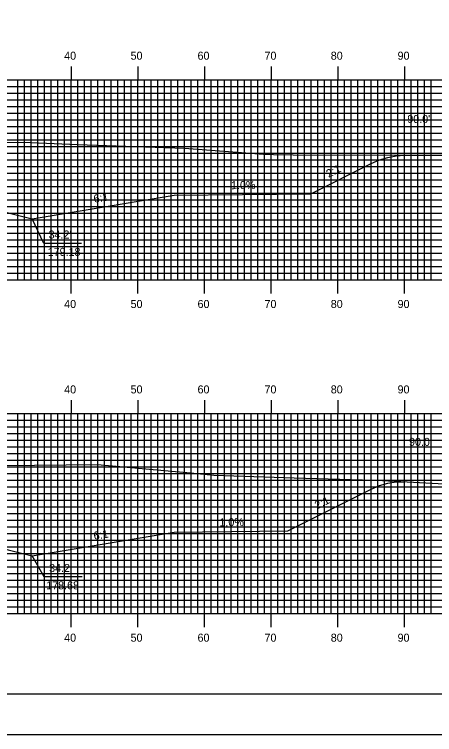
# Model space of a CAD drawing. Extents: x 1797207 to 1797550, y 442591 to 442811.
# Drawn here: x 1797404.4 to 1797467.5, y 442590.5 to 442698.5 of the extents above; entities that cross this region are included whole.
import ezdxf

# ---------------------------------------------------------------- set-up
doc = ezdxf.new("R2010")
doc.units = 0
for name, color, linetype in [('ANNOTATION', 7, 'Continuous'), ('BORDER', 7, 'Continuous'), ('D_Roadway_Centerline', 7, 'Continuous'), ('D_Roadway_SlopeLines', 7, 'Continuous'), ('D_Text_Standard', 7, 'Continuous'), ('H_V ANNOTATION', 7, 'Continuous'), ('MAJOR', 7, 'Continuous'), ('MINOR', 7, 'Continuous'), ('PLOT BOUNDARY', 7, 'Continuous'), ('S_Roadway_Centerline', 7, 'Continuous')]:
    doc.layers.add(name, color=color, linetype=linetype)

msp = doc.modelspace()

# ---------------------------------------------------------------- linework, layer by layer
at = {"layer": 'ANNOTATION'}
for points in [[(1797414.52, 442664.15), (1797408.83, 442664.15), (1797407.11, 442667.85)], [(1797414.6, 442614.18), (1797408.91, 442614.18), (1797407.11, 442617.35)]]:
    msp.add_lwpolyline(points, dxfattribs=at)
at = {"layer": 'BORDER'}
msp.add_lwpolyline([(1797223.33, 442596.67), (1797543.33, 442596.67), (1797543.33, 442806.67), (1797223.33, 442806.67)], close=True, dxfattribs=at)
at = {"layer": 'D_Roadway_Centerline'}
for points in [[(1797282.93, 442682.01), (1797284.18, 442681.93), (1797285.43, 442681.68), (1797286.68, 442681.29), (1797287.93, 442680.74), (1797305.44, 442671.99), (1797317.5, 442671.87), (1797338.76, 442668.33), (1797342.76, 442669.33), (1797352.93, 442671.87), (1797360.93, 442672.19), (1797372.93, 442671.95), (1797384.93, 442671.71), (1797392.93, 442671.39), (1797403.11, 442668.85), (1797407.11, 442667.85), (1797428.37, 442671.39), (1797448.91, 442671.59), (1797457.93, 442676.11), (1797459.18, 442676.65), (1797460.43, 442677.04), (1797461.68, 442677.28), (1797462.93, 442677.35)], [(1797282.93, 442632.85), (1797284.18, 442632.77), (1797285.43, 442632.53), (1797286.68, 442632.14), (1797287.93, 442631.59), (1797308.19, 442621.46), (1797317.5, 442621.37), (1797338.76, 442617.83), (1797342.76, 442618.83), (1797352.93, 442621.37), (1797360.93, 442621.69), (1797372.93, 442621.45), (1797384.93, 442621.21), (1797392.93, 442620.89), (1797403.11, 442618.35), (1797407.11, 442617.35), (1797428.37, 442620.89), (1797445.43, 442621.06), (1797457.93, 442627.31), (1797459.18, 442627.85), (1797460.43, 442628.22), (1797461.68, 442628.41), (1797462.93, 442628.43)]]:
    msp.add_lwpolyline(points, dxfattribs=at)
at = {"layer": 'D_Roadway_SlopeLines'}
for points in [[(1797428.37, 442671.39), (1797448.91, 442671.59), (1797457.93, 442676.11), (1797459.18, 442676.65), (1797460.43, 442677.04), (1797461.68, 442677.28), (1797462.93, 442677.35)], [(1797392.93, 442671.39), (1797407.11, 442667.85)], [(1797407.11, 442667.85), (1797428.37, 442671.39)], [(1797428.37, 442620.89), (1797445.43, 442621.06), (1797457.93, 442627.31), (1797459.18, 442627.85), (1797460.43, 442628.22), (1797461.68, 442628.41), (1797462.93, 442628.43)], [(1797392.93, 442620.89), (1797407.11, 442617.35)], [(1797407.11, 442617.35), (1797428.37, 442620.89)]]:
    msp.add_lwpolyline(points, dxfattribs=at)
at = {"layer": 'MAJOR'}
for p, q in [((1797412.93, 442690.67), (1797412.93, 442688.67)), ((1797422.93, 442690.67), (1797422.93, 442688.67)), ((1797432.93, 442690.67), (1797432.93, 442688.67)), ((1797442.93, 442690.67), (1797442.93, 442688.67)), ((1797452.93, 442690.67), (1797452.93, 442688.67)), ((1797462.93, 442690.67), (1797462.93, 442688.67)), ((1797232.93, 442688.67), (1797512.93, 442688.67)), ((1797232.93, 442688.67), (1797512.93, 442688.67)), ((1797412.93, 442658.67), (1797412.93, 442688.67)), ((1797422.93, 442658.67), (1797422.93, 442688.67)), ((1797432.93, 442658.67), (1797432.93, 442688.67)), ((1797442.93, 442658.67), (1797442.93, 442688.67)), ((1797452.93, 442658.67), (1797452.93, 442688.67)), ((1797462.93, 442658.67), (1797462.93, 442688.67)), ((1797232.93, 442683.67), (1797512.93, 442683.67)), ((1797232.93, 442678.67), (1797512.93, 442678.67)), ((1797232.93, 442673.67), (1797512.93, 442673.67)), ((1797232.93, 442668.67), (1797512.93, 442668.67)), ((1797232.93, 442663.67), (1797512.93, 442663.67)), ((1797232.93, 442658.67), (1797512.93, 442658.67)), ((1797232.93, 442658.67), (1797512.93, 442658.67)), ((1797412.93, 442656.66), (1797412.93, 442658.67)), ((1797422.93, 442656.66), (1797422.93, 442658.67)), ((1797432.93, 442656.66), (1797432.93, 442658.67)), ((1797442.93, 442656.66), (1797442.93, 442658.67)), ((1797452.93, 442656.66), (1797452.93, 442658.67)), ((1797462.93, 442656.66), (1797462.93, 442658.67)), ((1797412.93, 442640.67), (1797412.93, 442638.67)), ((1797422.93, 442640.67), (1797422.93, 442638.67)), ((1797432.93, 442640.67), (1797432.93, 442638.67)), ((1797442.93, 442640.67), (1797442.93, 442638.67)), ((1797452.93, 442640.67), (1797452.93, 442638.67)), ((1797462.93, 442640.67), (1797462.93, 442638.67)), ((1797232.93, 442638.67), (1797512.93, 442638.67)), ((1797232.93, 442638.67), (1797512.93, 442638.67)), ((1797412.93, 442608.67), (1797412.93, 442638.67)), ((1797422.93, 442608.67), (1797422.93, 442638.67)), ((1797432.93, 442608.67), (1797432.93, 442638.67)), ((1797442.93, 442608.67), (1797442.93, 442638.67)), ((1797452.93, 442608.67), (1797452.93, 442638.67)), ((1797462.93, 442608.67), (1797462.93, 442638.67)), ((1797232.93, 442633.67), (1797512.93, 442633.67)), ((1797232.93, 442628.67), (1797512.93, 442628.67)), ((1797232.93, 442623.67), (1797512.93, 442623.67)), ((1797232.93, 442618.67), (1797512.93, 442618.67)), ((1797232.93, 442613.67), (1797512.93, 442613.67)), ((1797232.93, 442608.67), (1797512.93, 442608.67)), ((1797232.93, 442608.67), (1797512.93, 442608.67)), ((1797412.93, 442606.66), (1797412.93, 442608.67)), ((1797422.93, 442606.66), (1797422.93, 442608.67)), ((1797432.93, 442606.66), (1797432.93, 442608.67)), ((1797442.93, 442606.66), (1797442.93, 442608.67)), ((1797452.93, 442606.66), (1797452.93, 442608.67)), ((1797462.93, 442606.66), (1797462.93, 442608.67))]:
    msp.add_line(p, q, dxfattribs=at)
at = {"layer": 'MINOR'}
for p, q in [((1797404.93, 442658.67), (1797404.93, 442688.67)), ((1797405.93, 442658.67), (1797405.93, 442688.67)), ((1797406.93, 442658.67), (1797406.93, 442688.67)), ((1797407.93, 442658.67), (1797407.93, 442688.67)), ((1797408.93, 442658.67), (1797408.93, 442688.67)), ((1797409.93, 442658.67), (1797409.93, 442688.67)), ((1797410.93, 442658.67), (1797410.93, 442688.67)), ((1797411.93, 442658.67), (1797411.93, 442688.67)), ((1797413.93, 442658.67), (1797413.93, 442688.67)), ((1797414.93, 442658.67), (1797414.93, 442688.67)), ((1797415.93, 442658.67), (1797415.93, 442688.67)), ((1797416.93, 442658.67), (1797416.93, 442688.67)), ((1797417.93, 442658.67), (1797417.93, 442688.67)), ((1797418.93, 442658.67), (1797418.93, 442688.67)), ((1797419.93, 442658.67), (1797419.93, 442688.67)), ((1797420.93, 442658.67), (1797420.93, 442688.67)), ((1797421.93, 442658.67), (1797421.93, 442688.67)), ((1797423.93, 442658.67), (1797423.93, 442688.67)), ((1797424.93, 442658.67), (1797424.93, 442688.67)), ((1797425.93, 442658.67), (1797425.93, 442688.67)), ((1797426.93, 442658.67), (1797426.93, 442688.67)), ((1797427.93, 442658.67), (1797427.93, 442688.67)), ((1797428.93, 442658.67), (1797428.93, 442688.67)), ((1797429.93, 442658.67), (1797429.93, 442688.67)), ((1797430.93, 442658.67), (1797430.93, 442688.67)), ((1797431.93, 442658.67), (1797431.93, 442688.67)), ((1797433.93, 442658.67), (1797433.93, 442688.67)), ((1797434.93, 442658.67), (1797434.93, 442688.67)), ((1797435.93, 442658.67), (1797435.93, 442688.67)), ((1797436.93, 442658.67), (1797436.93, 442688.67)), ((1797437.93, 442658.67), (1797437.93, 442688.67)), ((1797438.93, 442658.67), (1797438.93, 442688.67)), ((1797439.93, 442658.67), (1797439.93, 442688.67)), ((1797440.93, 442658.67), (1797440.93, 442688.67)), ((1797441.93, 442658.67), (1797441.93, 442688.67)), ((1797443.93, 442658.67), (1797443.93, 442688.67)), ((1797444.93, 442658.67), (1797444.93, 442688.67)), ((1797445.93, 442658.67), (1797445.93, 442688.67)), ((1797446.93, 442658.67), (1797446.93, 442688.67)), ((1797447.93, 442658.67), (1797447.93, 442688.67)), ((1797448.93, 442658.67), (1797448.93, 442688.67)), ((1797449.93, 442658.67), (1797449.93, 442688.67)), ((1797450.93, 442658.67), (1797450.93, 442688.67)), ((1797451.93, 442658.67), (1797451.93, 442688.67)), ((1797453.93, 442658.67), (1797453.93, 442688.67)), ((1797454.93, 442658.67), (1797454.93, 442688.67)), ((1797455.93, 442658.67), (1797455.93, 442688.67)), ((1797456.93, 442658.67), (1797456.93, 442688.67)), ((1797457.93, 442658.67), (1797457.93, 442688.67)), ((1797458.93, 442658.67), (1797458.93, 442688.67)), ((1797459.93, 442658.67), (1797459.93, 442688.67)), ((1797460.93, 442658.67), (1797460.93, 442688.67)), ((1797461.93, 442658.67), (1797461.93, 442688.67)), ((1797463.93, 442658.67), (1797463.93, 442688.67)), ((1797464.93, 442658.67), (1797464.93, 442688.67)), ((1797465.93, 442658.67), (1797465.93, 442688.67)), ((1797466.93, 442658.67), (1797466.93, 442688.67)), ((1797232.93, 442687.67), (1797512.93, 442687.67)), ((1797232.93, 442686.67), (1797512.93, 442686.67)), ((1797232.93, 442685.67), (1797512.93, 442685.67)), ((1797232.93, 442684.67), (1797512.93, 442684.67)), ((1797232.93, 442682.67), (1797512.93, 442682.67)), ((1797232.93, 442681.67), (1797512.93, 442681.67)), ((1797232.93, 442680.67), (1797512.93, 442680.67)), ((1797232.93, 442679.67), (1797512.93, 442679.67)), ((1797232.93, 442677.67), (1797512.93, 442677.67)), ((1797232.93, 442676.67), (1797512.93, 442676.67)), ((1797232.93, 442675.67), (1797512.93, 442675.67)), ((1797232.93, 442674.67), (1797512.93, 442674.67)), ((1797232.93, 442672.67), (1797512.93, 442672.67)), ((1797232.93, 442671.67), (1797512.93, 442671.67)), ((1797232.93, 442670.67), (1797512.93, 442670.67)), ((1797232.93, 442669.67), (1797512.93, 442669.67)), ((1797232.93, 442667.67), (1797512.93, 442667.67)), ((1797232.93, 442666.67), (1797512.93, 442666.67)), ((1797232.93, 442665.67), (1797512.93, 442665.67)), ((1797232.93, 442664.67), (1797512.93, 442664.67)), ((1797232.93, 442662.67), (1797512.93, 442662.67)), ((1797232.93, 442661.67), (1797512.93, 442661.67)), ((1797232.93, 442660.67), (1797512.93, 442660.67)), ((1797232.93, 442659.67), (1797512.93, 442659.67)), ((1797404.93, 442608.67), (1797404.93, 442638.67)), ((1797405.93, 442608.67), (1797405.93, 442638.67)), ((1797406.93, 442608.67), (1797406.93, 442638.67)), ((1797407.93, 442608.67), (1797407.93, 442638.67)), ((1797408.93, 442608.67), (1797408.93, 442638.67)), ((1797409.93, 442608.67), (1797409.93, 442638.67)), ((1797410.93, 442608.67), (1797410.93, 442638.67)), ((1797411.93, 442608.67), (1797411.93, 442638.67)), ((1797413.93, 442608.67), (1797413.93, 442638.67)), ((1797414.93, 442608.67), (1797414.93, 442638.67)), ((1797415.93, 442608.67), (1797415.93, 442638.67)), ((1797416.93, 442608.67), (1797416.93, 442638.67)), ((1797417.93, 442608.67), (1797417.93, 442638.67)), ((1797418.93, 442608.67), (1797418.93, 442638.67)), ((1797419.93, 442608.67), (1797419.93, 442638.67)), ((1797420.93, 442608.67), (1797420.93, 442638.67)), ((1797421.93, 442608.67), (1797421.93, 442638.67)), ((1797423.93, 442608.67), (1797423.93, 442638.67)), ((1797424.93, 442608.67), (1797424.93, 442638.67)), ((1797425.93, 442608.67), (1797425.93, 442638.67)), ((1797426.93, 442608.67), (1797426.93, 442638.67)), ((1797427.93, 442608.67), (1797427.93, 442638.67)), ((1797428.93, 442608.67), (1797428.93, 442638.67)), ((1797429.93, 442608.67), (1797429.93, 442638.67)), ((1797430.93, 442608.67), (1797430.93, 442638.67)), ((1797431.93, 442608.67), (1797431.93, 442638.67)), ((1797433.93, 442608.67), (1797433.93, 442638.67)), ((1797434.93, 442608.67), (1797434.93, 442638.67)), ((1797435.93, 442608.67), (1797435.93, 442638.67)), ((1797436.93, 442608.67), (1797436.93, 442638.67)), ((1797437.93, 442608.67), (1797437.93, 442638.67)), ((1797438.93, 442608.67), (1797438.93, 442638.67)), ((1797439.93, 442608.67), (1797439.93, 442638.67)), ((1797440.93, 442608.67), (1797440.93, 442638.67)), ((1797441.93, 442608.67), (1797441.93, 442638.67)), ((1797443.93, 442608.67), (1797443.93, 442638.67)), ((1797444.93, 442608.67), (1797444.93, 442638.67)), ((1797445.93, 442608.67), (1797445.93, 442638.67)), ((1797446.93, 442608.67), (1797446.93, 442638.67)), ((1797447.93, 442608.67), (1797447.93, 442638.67)), ((1797448.93, 442608.67), (1797448.93, 442638.67)), ((1797449.93, 442608.67), (1797449.93, 442638.67)), ((1797450.93, 442608.67), (1797450.93, 442638.67)), ((1797451.93, 442608.67), (1797451.93, 442638.67)), ((1797453.93, 442608.67), (1797453.93, 442638.67)), ((1797454.93, 442608.67), (1797454.93, 442638.67)), ((1797455.93, 442608.67), (1797455.93, 442638.67)), ((1797456.93, 442608.67), (1797456.93, 442638.67)), ((1797457.93, 442608.67), (1797457.93, 442638.67)), ((1797458.93, 442608.67), (1797458.93, 442638.67)), ((1797459.93, 442608.67), (1797459.93, 442638.67)), ((1797460.93, 442608.67), (1797460.93, 442638.67)), ((1797461.93, 442608.67), (1797461.93, 442638.67)), ((1797463.93, 442608.67), (1797463.93, 442638.67)), ((1797464.93, 442608.67), (1797464.93, 442638.67)), ((1797465.93, 442608.67), (1797465.93, 442638.67)), ((1797466.93, 442608.67), (1797466.93, 442638.67)), ((1797232.93, 442637.67), (1797512.93, 442637.67)), ((1797232.93, 442636.67), (1797512.93, 442636.67)), ((1797232.93, 442635.67), (1797512.93, 442635.67)), ((1797232.93, 442634.67), (1797512.93, 442634.67)), ((1797232.93, 442632.67), (1797512.93, 442632.67)), ((1797232.93, 442631.67), (1797512.93, 442631.67)), ((1797232.93, 442630.67), (1797512.93, 442630.67)), ((1797232.93, 442629.67), (1797512.93, 442629.67)), ((1797232.93, 442627.67), (1797512.93, 442627.67)), ((1797232.93, 442626.67), (1797512.93, 442626.67)), ((1797232.93, 442625.67), (1797512.93, 442625.67)), ((1797232.93, 442624.67), (1797512.93, 442624.67)), ((1797232.93, 442622.67), (1797512.93, 442622.67)), ((1797232.93, 442621.67), (1797512.93, 442621.67)), ((1797232.93, 442620.67), (1797512.93, 442620.67)), ((1797232.93, 442619.67), (1797512.93, 442619.67)), ((1797232.93, 442617.67), (1797512.93, 442617.67)), ((1797232.93, 442616.67), (1797512.93, 442616.67)), ((1797232.93, 442615.67), (1797512.93, 442615.67)), ((1797232.93, 442614.67), (1797512.93, 442614.67)), ((1797232.93, 442612.67), (1797512.93, 442612.67)), ((1797232.93, 442611.67), (1797512.93, 442611.67)), ((1797232.93, 442610.67), (1797512.93, 442610.67)), ((1797232.93, 442609.67), (1797512.93, 442609.67))]:
    msp.add_line(p, q, dxfattribs=at)
at = {"layer": 'PLOT BOUNDARY'}
msp.add_lwpolyline([(1797207.14, 442590.55), (1797547.14, 442590.55), (1797547.14, 442810.55), (1797207.14, 442810.55)], close=True, dxfattribs=at)
at = {"layer": 'S_Roadway_Centerline'}
for points in [[(1797331.88, 442680.97), (1797354, 442680.91), (1797358.39, 442680.88), (1797359.76, 442680.87), (1797360.75, 442680.94), (1797365.87, 442680.66), (1797379.87, 442680.16), (1797382.65, 442680.04), (1797387.21, 442679.84), (1797395.87, 442679.55), (1797401.77, 442679.34), (1797406.89, 442679.28), (1797413.91, 442678.99), (1797421.16, 442678.73), (1797429.95, 442678.41), (1797441.77, 442677.53), (1797443.31, 442677.47), (1797446.26, 442677.4), (1797461.77, 442677.35), (1797469.61, 442677.36)], [(1797340.53, 442631.94), (1797346.87, 442631.81), (1797356.03, 442631.71), (1797363.94, 442631.57), (1797374.47, 442631.47), (1797375.81, 442631.45), (1797376.78, 442631.38), (1797384.99, 442631.2), (1797391.85, 442631.02), (1797396.99, 442630.8), (1797399.46, 442630.72), (1797402.74, 442630.89), (1797416.89, 442631.01), (1797430.84, 442629.76), (1797434.32, 442629.44), (1797437.34, 442629.3), (1797446.4, 442629.01), (1797458.35, 442628.67), (1797458.5, 442628.66), (1797458.68, 442628.65), (1797478.23, 442627.63)]]:
    msp.add_lwpolyline(points, dxfattribs=at)

# ---------------------------------------------------------------- texts
at = {"layer": 'ANNOTATION'}
for s, rotation, p in [('2:1', 26.5651, (1797451.56, 442673.96)), ('1.0%', 0.5729, (1797436.93, 442672.27)), ('6:1', 9.4624, (1797416.41, 442670.22)), ('2:1', 26.5651, (1797449.83, 442624.29)), ('1.0%', 0.5729, (1797435.19, 442621.76)), ('6:1', 9.4625, (1797416.41, 442619.72))]:
    msp.add_text(s, height=1.2, rotation=rotation, dxfattribs=at).set_placement(p)
for s, p in [("34.2'", (1797409.56, 442664.88)), ('179.18', (1797409.43, 442662.28)), ("34.2'", (1797409.64, 442614.91)), ('178.68', (1797409.21, 442612.31))]:
    msp.add_text(s, height=1.2, dxfattribs=at).set_placement(p)
at = {"layer": 'D_Text_Standard'}
for p in [(1797463.36, 442682.19), (1797463.62, 442633.81)]:
    msp.add_text("90.0'", height=1.2, dxfattribs=at).set_placement(p)
at = {"layer": 'H_V ANNOTATION'}
for s, p in [('40', (1797411.9, 442691.67)), ('50', (1797421.86, 442691.67)), ('60', (1797431.9, 442691.67)), ('70', (1797441.94, 442691.67)), ('80', (1797451.88, 442691.67)), ('90', (1797461.9, 442691.67)), ('40', (1797411.9, 442654.47)), ('50', (1797421.86, 442654.47)), ('60', (1797431.9, 442654.47)), ('70', (1797441.94, 442654.47)), ('80', (1797451.88, 442654.47)), ('90', (1797461.9, 442654.47)), ('40', (1797411.9, 442641.67)), ('50', (1797421.86, 442641.67)), ('60', (1797431.9, 442641.67)), ('70', (1797441.94, 442641.67)), ('80', (1797451.88, 442641.67)), ('90', (1797461.9, 442641.67)), ('40', (1797411.9, 442604.47)), ('50', (1797421.86, 442604.47)), ('60', (1797431.9, 442604.47)), ('70', (1797441.94, 442604.47)), ('80', (1797451.88, 442604.47)), ('90', (1797461.9, 442604.47))]:
    msp.add_text(s, height=1.2, dxfattribs=at).set_placement(p)

doc.saveas('drawing.dxf')
